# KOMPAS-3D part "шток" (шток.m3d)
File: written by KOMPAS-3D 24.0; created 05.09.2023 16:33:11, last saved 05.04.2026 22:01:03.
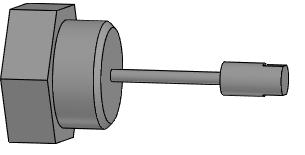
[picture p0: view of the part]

Document properties: Полное имя файла: E:\Работа\Зайцев\Аксессуары для пневмоприводов\Электропневматические позиционеры DN.ru\ЭИП Электропневматический позиционер DN.ru\ЭИП-1500 Электропневматический позиционер DN.ru\5-25\шток.m3d

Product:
- Part/product: шток
    Масса: 0.134738

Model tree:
1. Операция без истории:1
2. Эскиз:1  (with: Грань.Операция без истории:1)
3. Элемент выдавливания:1
     Расстояние 2 = 107.1
4. Эскиз:2
5. Элемент выдавливания:2
6. Эскиз:3
7. Элемент вращения:1
     Угол 1 = 360
8. Эскиз:4  (with: Грань.Элемент вращения:1)
9. Элемент выдавливания:3
10. Фаска:1  (with: Ребро.Элемент вращения:1)
     Угол = 45; Длина 1 = 1.5; Длина 2 = 1.5
11. Эскиз:5  (with: Грань.Элемент вращения:1)
12. Элемент выдавливания:4
     Расстояние 2 = 5

Expressions: 8.5+3; 54-v81/2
